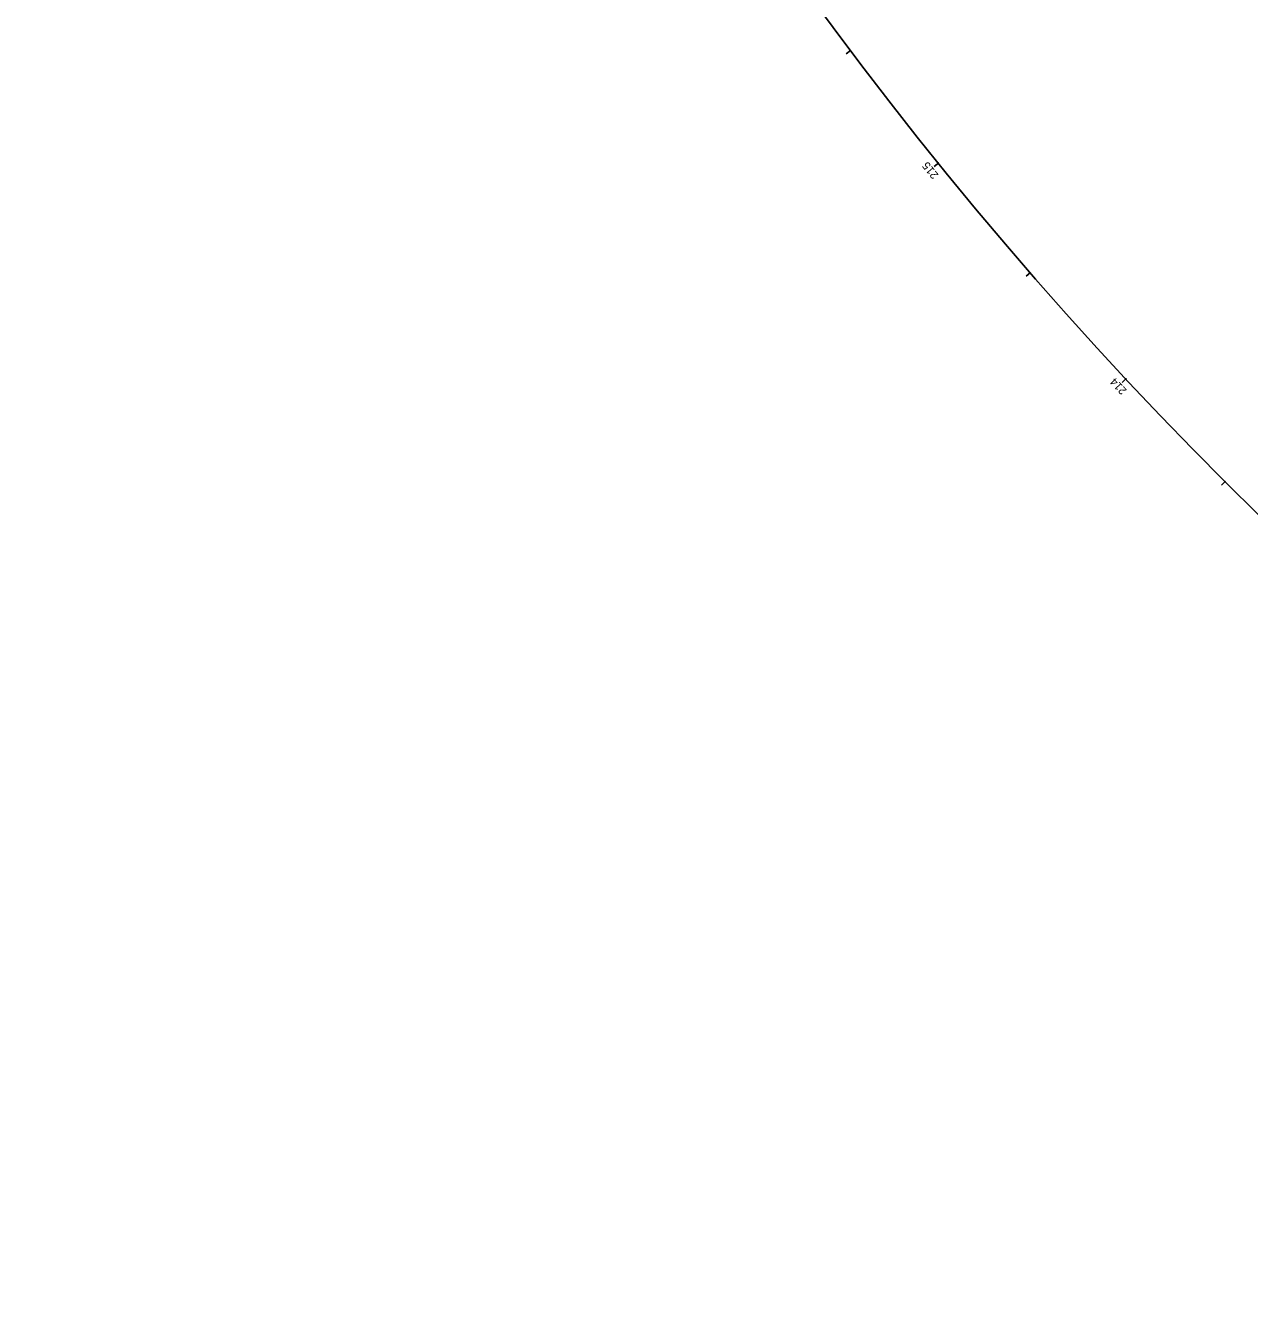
# Model space of a CAD drawing. Extents: x 1454426 to 1455277, y 587472 to 590476.
# Drawn here: x 1454431 to 1454859.5, y 587472.5 to 587916.7 of the extents above; entities that cross this region are included whole.
import ezdxf

# ---------------------------------------------------------------- set-up
doc = ezdxf.new("R2010")
doc.units = 0
for name, color, linetype in [('Default', 7, 'Continuous'), ('GT_Target_Soil_Boring', 7, 'Continuous'), ('PV_P_Saw_Cut_Line', 7, 'Continuous'), ('SC_Scratch1', 7, 'Continuous'), ('SC_Scratch2', 7, 'Continuous'), ('SC_Scratch3', 7, 'Continuous')]:
    doc.layers.add(name, color=color, linetype=linetype)

msp = doc.modelspace()

# ---------------------------------------------------------------- linework, layer by layer
at = {"layer": 'Default'}
for centre in [(1454750.67, 587868.51), (1454750.67, 587868.51), (1454750.67, 587868.51), (1454816.3, 587793.09), (1454816.3, 587793.09), (1454816.3, 587793.09)]:
    msp.add_circle(centre, 0.0000833, dxfattribs=at)
at = {"layer": 'GT_Target_Soil_Boring'}
msp.add_arc((1455863.38, 588770.51), 1432.39, 161.3175, 244.97965, dxfattribs=at)
at = {"layer": 'PV_P_Saw_Cut_Line'}
msp.add_arc((1455863.38, 588770.51), 1432.39, 161.3175, 244.97965, dxfattribs=at)
at = {"layer": 'SC_Scratch1'}
for p, q in [((1454719.86, 587907.9), (1454718.27, 587906.69)), ((1454750.67, 587868.51), (1454749.11, 587867.25)), ((1454782.82, 587830.23), (1454781.32, 587828.92)), ((1454816.3, 587793.09), (1454814.84, 587791.73)), ((1454851.05, 587757.14), (1454849.63, 587755.73))]:
    msp.add_line(p, q, dxfattribs=at)
at = {"layer": 'SC_Scratch2'}
for p, q in [((1454719.86, 587907.9), (1454718.27, 587906.69)), ((1454750.67, 587868.51), (1454749.11, 587867.25)), ((1454782.82, 587830.23), (1454781.32, 587828.92)), ((1454816.3, 587793.09), (1454814.84, 587791.73)), ((1454851.05, 587757.14), (1454849.63, 587755.73))]:
    msp.add_line(p, q, dxfattribs=at)
at = {"layer": 'SC_Scratch3'}
for p, q in [((1454719.86, 587907.9), (1454718.27, 587906.69)), ((1454750.67, 587868.51), (1454749.11, 587867.25)), ((1454782.82, 587830.23), (1454781.32, 587828.92)), ((1454816.3, 587793.09), (1454814.84, 587791.73)), ((1454851.05, 587757.14), (1454849.63, 587755.73))]:
    msp.add_line(p, q, dxfattribs=at)

# ---------------------------------------------------------------- texts
at = {"layer": 'SC_Scratch1'}
for s, rotation, p in [('215', 129.0292, (1454750.76, 587864.35)), ('214', 133.0292, (1454816.68, 587789.02))]:
    msp.add_text(s, height=2.8, rotation=rotation, dxfattribs=at).set_placement(p)
at = {"layer": 'SC_Scratch2'}
for s, rotation, p in [('215', 129.0292, (1454750.76, 587864.35)), ('214', 133.0292, (1454816.68, 587789.02))]:
    msp.add_text(s, height=2.8, rotation=rotation, dxfattribs=at).set_placement(p)
at = {"layer": 'SC_Scratch3'}
for s, rotation, p in [('215', 129.0292, (1454750.76, 587864.35)), ('214', 133.0292, (1454816.68, 587789.02))]:
    msp.add_text(s, height=2.8, rotation=rotation, dxfattribs=at).set_placement(p)

doc.saveas('drawing.dxf')
